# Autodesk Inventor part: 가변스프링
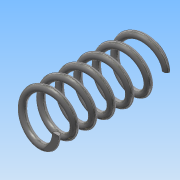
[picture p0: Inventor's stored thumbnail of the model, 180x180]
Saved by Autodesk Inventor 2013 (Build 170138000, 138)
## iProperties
Created: 2015-05
Part Number: 가변스프링
Material: 강철, 탄소
Document SubType Name: Modeling
Designer: Administrator
Density: 7.87 g/cm^3
Mass: 11.504 g
Surface Area: 23.7345 cm^2
Volume: 1.46175 cm^3
Author: Administrator
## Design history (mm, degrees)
sketch "스케치1"
  geometry: L1 (0, 0)-(8, 0); L2 (8, 0)-(8, 42); L3 (8, 42)-(0, 42); L4 (0, 42)-(0, 0); C1 r 1.25 at (8, 0)
  constraints: 8 end point, 2 parallel, 1 centre point, 1 coincident, 1 horizontal, 1 perpendicular
  dimensions: "d0" = 42 distance of L3.end L1.start (derived); "d1" = 16 diameter of L2 L4; "d2" = 2.5 diameter of C1
feature "코일1" sketch "스케치1" pitch "d3" = 10; turns "d5" = 6; dims "d4" = 42 (= d0), "d6" = 0, angle "d7" = 90 deg, angle "d8" = 90 deg, "d9" = 0, "d10" = 0
sketch "스케치2"
  geometry: L1 (0, 12.5)-(42, 12.5); L2 (42, 12.5)-(42, -12.5); L3 (42, -12.5)-(0, -12.5); L4 (0, -12.5)-(0, 12.5); 4 further points
  constraints: 8 end point, 2 coincident, 2 midpoint, 2 parallel, 1 horizontal, 1 perpendicular
  dimensions: "d11" = 42 distance of L2.end L3.end (derived); "d12" = 25 distance of L1.end L2.end
extrude "돌출1" sketch "스케치2" stored distance "d13" = 10; taper "d14" = 0 deg
node "솔리드1"
